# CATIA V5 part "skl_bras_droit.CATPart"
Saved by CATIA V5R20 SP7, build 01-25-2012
Part number: skl_bras_droit
Publications: "Axe_pivot_bras_droit_bâti", "Axe_pivot_bras_droit_patin_droit", "Axe_pivot_bras_droit_biellette_droite", "Plan.1"
Bounding box of the stored display mesh (mm): x 0 to 524.226, y -390 to 700, z 0 to 20
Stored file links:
  U:\IAO\thinkmotion catia2\skl_bras_droit.CATPart
  U:\IAO\thinkmotion catia2\skl_862_adubourgno.CATProduct
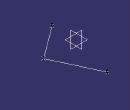
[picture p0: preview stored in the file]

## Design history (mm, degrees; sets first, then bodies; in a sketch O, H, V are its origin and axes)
Set1
  Point1 "F": linked copy from another document
  Point2 "J": linked copy from another document
  Point3 "C": linked copy from another document
  Plane1: linked copy from another document
Set2
  Line1: type PtPt, FirstPoint Point1, SecondPoint Point2
  Line2: type PtPt, FirstPoint Point2, SecondPoint Point3
  Line3 "Axe_pivot_bras_droit_biellette_droite": type Normal, RefPoint Point1, RefSkin Plane1, Start 0, End 20
  Line4 "Axe_pivot_bras_droit_patin_droit": type Normal, RefPoint Point2, RefSkin Plane1, Start 0, End 20
  Line5 "Axe_pivot_bras_droit_bâti": type Normal, RefPoint Point3, RefSkin Plane1, Start 0, End 20
Body1 (main body)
